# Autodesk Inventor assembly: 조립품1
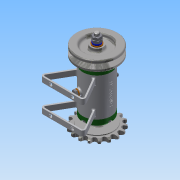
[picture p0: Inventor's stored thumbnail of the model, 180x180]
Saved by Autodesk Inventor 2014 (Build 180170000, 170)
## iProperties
Created: 2016-03
Part Number: 조립품1
Document SubType Name: Assembly
Designer: 406-0014
Author: 406-0014
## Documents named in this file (16)
- C:\Users\406-0014\Desktop\460307V1008\조립품1.iam
- C:\Users\406-0014\Desktop\460307V1008\본체.ipt
- C:\Users\406-0014\Desktop\460307V1008\축.ipt
- C:\Users\406-0014\Desktop\460307V1008\베어링 15 x 32 x 9.ipt
- C:\Users\406-0014\Desktop\460307V1008\커버.ipt
- C:\Users\406-0014\Desktop\460307V1008\오일 실 15 25 7.ipt
- C:\Users\406-0014\Desktop\460307V1008\V벨트풀리.ipt
- C:\Users\406-0014\Desktop\460307V1008\스프로킷.ipt
- C:\Users\406-0014\Desktop\460307V1008\키 3 x 3 x 12.ipt
- C:\Users\406-0014\Desktop\460307V1008\너트 M 8.ipt
- C:\Users\406-0014\Desktop\460307V1008\와셔 8x17.ipt
- C:\Users\406-0014\Desktop\460307V1008\스프링와셔 8.ipt
- C:\Users\406-0014\Desktop\460307V1008\니플 M 6 x 0.75.ipt
- C:\Users\406-0014\Desktop\460307V1008\와셔 6x11.5.ipt
- C:\Users\406-0014\Desktop\460307V1008\볼트 M 6 x 8.ipt
- C:\Users\406-0014\Desktop\460307V1008\볼트 M4 x 12.ipt
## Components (10 placed, 3 different names)
1. KS B 2023 6002 - 15 x 32 x 9:1
2. KS B 2023 6002 - 15 x 32 x 9:2
3. V벨트풀리:1
4. ISO 4762 M4 x 12:1
5. ISO 4762 M4 x 12:2
6. ISO 4762 M4 x 12:3
7. ISO 4762 M4 x 12:4
8. ISO 4762 M4 x 12:5
9. ISO 4762 M4 x 12:6
10. ISO 4762 M4 x 12:7
## Named parameters: d24_d20 = 0, d25_d21 = 0, d26_d22 = 0
